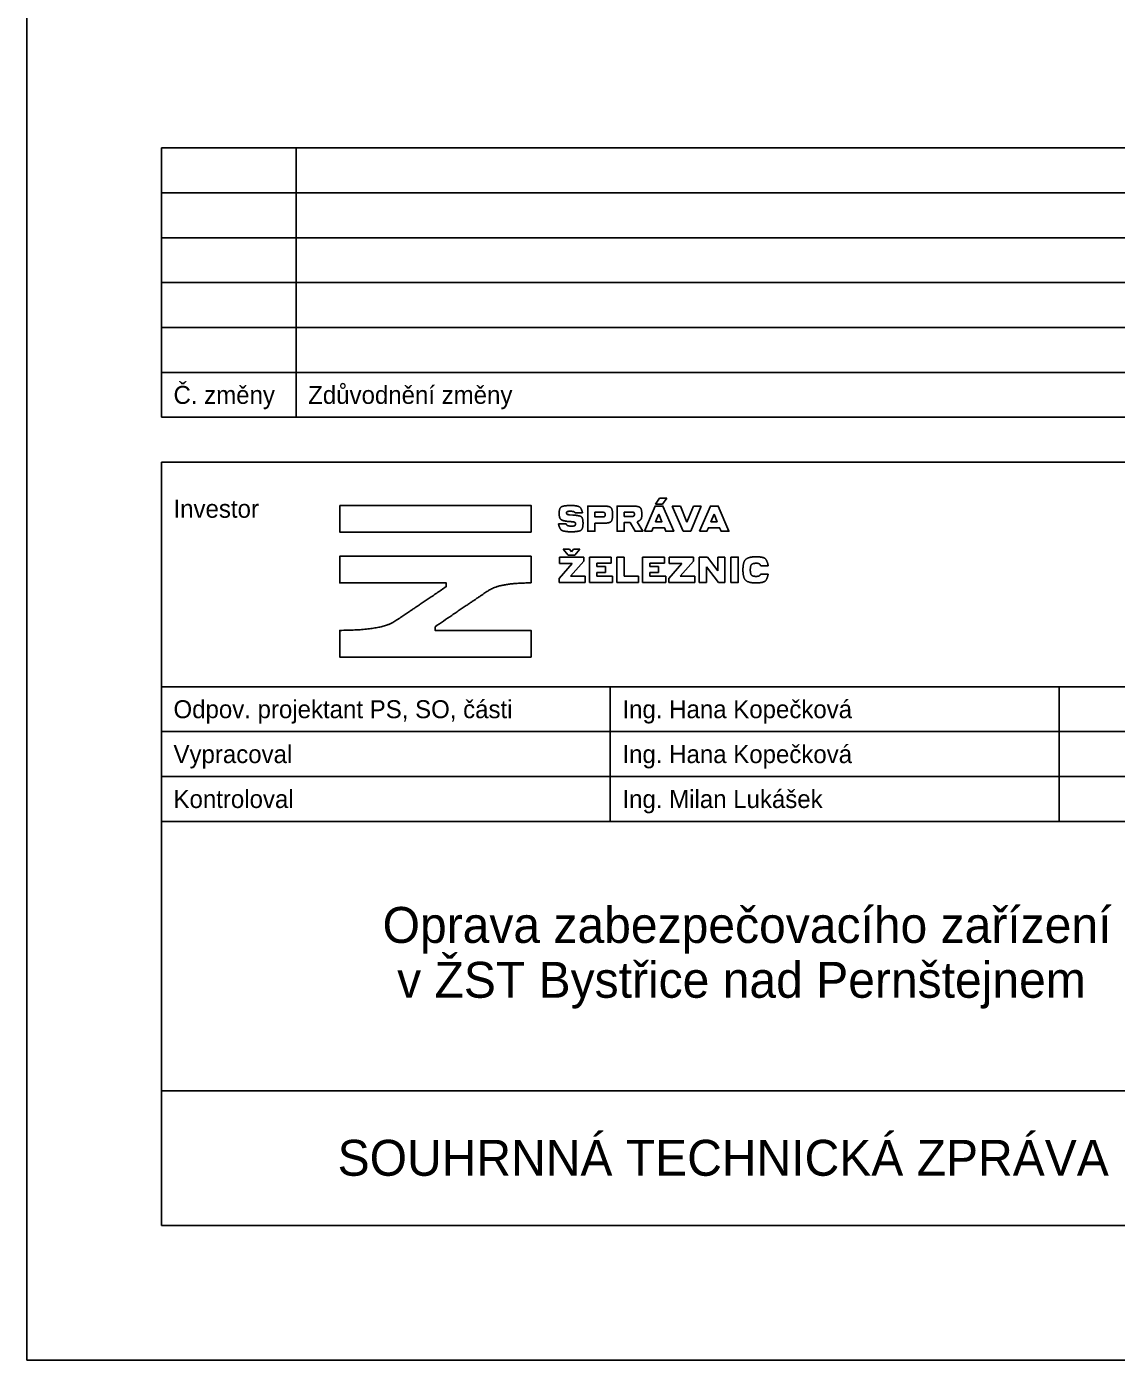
# Model space of a CAD drawing. Extents: x -790471 to -790261, y -984666 to -984369.
# Drawn here: x -790470.6 to -790349.2, y -984665.6 to -984517.1 of the extents above; entities that cross this region are included whole.
import ezdxf

# ---------------------------------------------------------------- set-up
doc = ezdxf.new("R2010")
doc.units = 0
for name, color, linetype in [('logo_sprava_zeleznic', 7, 'Continuous'), ('Ramečky', 7, 'Continuous'), ('Rámečky-tisk', 7, 'Continuous'), ('Text', 7, 'Continuous'), ('Text barevný', 7, 'Continuous')]:
    doc.layers.add(name, color=color, linetype=linetype)

msp = doc.modelspace()

# ---------------------------------------------------------------- linework, layer by layer
at = {"layer": 'logo_sprava_zeleznic'}
for p, q in [((-790400.56, -984570.26), (-790400.12, -984569.6)), ((-790400.12, -984569.6), (-790399.3, -984569.6)), ((-790399.3, -984569.6), (-790399.78, -984570.26)), ((-790409.51, -984571.23), (-790408.69, -984571.23)), ((-790399.78, -984570.26), (-790400.56, -984570.26)), ((-790398.7, -984570.48), (-790397.76, -984570.48)), ((-790397.49, -984573.29), (-790398.7, -984570.48)), ((-790397.76, -984570.48), (-790397.05, -984572.28)), ((-790397.05, -984572.28), (-790396.34, -984570.48)), ((-790395.49, -984570.48), (-790396.64, -984573.29)), ((-790396.34, -984570.48), (-790395.49, -984570.48)), ((-790410.51, -984572.45), (-790411.36, -984572.45)), ((-790409.76, -984571.48), (-790410.15, -984571.45)), ((-790396.64, -984573.29), (-790397.49, -984573.29)), ((-790410.29, -984575.96), (-790410.83, -984575.28)), ((-790410.83, -984575.28), (-790410.14, -984575.28)), ((-790410.14, -984575.28), (-790409.91, -984575.56)), ((-790409.91, -984575.56), (-790409.68, -984575.28)), ((-790409.68, -984575.28), (-790408.97, -984575.28)), ((-790408.97, -984575.28), (-790409.53, -984575.96)), ((-790411.3, -984578.53), (-790409.84, -984576.86)), ((-790411.26, -984576.17), (-790408.55, -984576.17)), ((-790411.26, -984576.86), (-790411.26, -984576.17)), ((-790409.84, -984576.86), (-790411.26, -984576.86)), ((-790409.53, -984575.96), (-790410.29, -984575.96)), ((-790408.55, -984576.63), (-790410.02, -984578.29)), ((-790408.55, -984576.17), (-790408.55, -984576.63)), ((-790407.92, -984576.17), (-790405.49, -984576.17)), ((-790407.92, -984578.99), (-790407.92, -984576.17)), ((-790405.49, -984576.83), (-790407.1, -984576.83)), ((-790407.1, -984576.83), (-790407.1, -984577.2)), ((-790407.1, -984577.2), (-790406.14, -984577.2)), ((-790406.14, -984577.2), (-790406.14, -984577.87)), ((-790405.49, -984576.17), (-790405.49, -984576.83)), ((-790404.86, -984576.17), (-790404.05, -984576.17)), ((-790404.86, -984578.99), (-790404.86, -984576.17)), ((-790404.05, -984576.17), (-790404.05, -984578.28)), ((-790401.99, -984576.17), (-790399.57, -984576.17)), ((-790401.99, -984578.99), (-790401.99, -984576.17)), ((-790399.57, -984576.83), (-790401.18, -984576.83)), ((-790401.18, -984576.83), (-790401.18, -984577.2)), ((-790401.18, -984577.2), (-790400.22, -984577.2)), ((-790400.22, -984577.2), (-790400.22, -984577.87)), ((-790399.57, -984576.17), (-790399.57, -984576.83)), ((-790399.07, -984578.53), (-790397.61, -984576.86)), ((-790399.03, -984576.17), (-790396.33, -984576.17)), ((-790399.03, -984576.86), (-790399.03, -984576.17)), ((-790397.61, -984576.86), (-790399.03, -984576.86)), ((-790396.33, -984576.63), (-790397.8, -984578.29)), ((-790396.33, -984576.17), (-790396.33, -984576.63)), ((-790395.69, -984576.17), (-790394.78, -984576.17)), ((-790395.69, -984578.99), (-790395.69, -984576.17)), ((-790393.53, -984578.99), (-790394.89, -984577.26)), ((-790394.89, -984577.26), (-790394.89, -984578.99)), ((-790394.78, -984576.17), (-790393.63, -984577.68)), ((-790393.63, -984577.68), (-790393.63, -984576.17)), ((-790393.63, -984576.17), (-790392.85, -984576.17)), ((-790392.85, -984576.17), (-790392.85, -984578.99)), ((-790388.84, -984577.12), (-790388.01, -984577.12)), ((-790411.3, -984578.99), (-790411.3, -984578.53)), ((-790410.02, -984578.29), (-790408.39, -984578.29)), ((-790408.39, -984578.29), (-790408.39, -984578.99)), ((-790406.14, -984577.87), (-790407.1, -984577.87)), ((-790407.1, -984577.87), (-790407.1, -984578.3)), ((-790407.1, -984578.3), (-790405.34, -984578.3)), ((-790405.34, -984578.3), (-790405.34, -984578.99)), ((-790404.05, -984578.28), (-790402.47, -984578.28)), ((-790402.47, -984578.28), (-790402.47, -984578.99)), ((-790400.22, -984577.87), (-790401.18, -984577.87)), ((-790401.18, -984577.87), (-790401.18, -984578.3)), ((-790401.18, -984578.3), (-790399.41, -984578.3)), ((-790399.41, -984578.3), (-790399.41, -984578.99)), ((-790399.07, -984578.99), (-790399.07, -984578.53)), ((-790397.8, -984578.29), (-790396.16, -984578.29)), ((-790396.16, -984578.29), (-790396.16, -984578.99)), ((-790388.01, -984578.05), (-790388.83, -984578.05)), ((-790408.39, -984578.99), (-790411.3, -984578.99)), ((-790405.34, -984578.99), (-790407.92, -984578.99)), ((-790402.47, -984578.99), (-790404.86, -984578.99)), ((-790399.41, -984578.99), (-790401.99, -984578.99)), ((-790396.16, -984578.99), (-790399.07, -984578.99)), ((-790394.89, -984578.99), (-790395.69, -984578.99)), ((-790392.85, -984578.99), (-790393.53, -984578.99))]:
    msp.add_line(p, q, dxfattribs=at)
for points in [[(-790435.73, -984570.4), (-790414.41, -984570.4), (-790414.41, -984573.38), (-790435.73, -984573.38)], [(-790401.8, -984573.29), (-790400.98, -984573.29), (-790400.82, -984572.89), (-790399.57, -984572.89), (-790399.41, -984573.29), (-790398.53, -984573.29), (-790399.73, -984570.48), (-790400.6, -984570.48)], [(-790395.65, -984573.29), (-790394.83, -984573.29), (-790394.66, -984572.89), (-790393.42, -984572.89), (-790393.26, -984573.29), (-790392.38, -984573.29), (-790393.57, -984570.48), (-790394.45, -984570.48)], [(-790400.19, -984571.39), (-790399.85, -984572.23), (-790400.54, -984572.23)], [(-790394.04, -984571.39), (-790393.7, -984572.23), (-790394.39, -984572.23)], [(-790392.16, -984576.17), (-790391.35, -984576.17), (-790391.35, -984578.99), (-790392.16, -984578.99)]]:
    msp.add_lwpolyline(points, close=True, dxfattribs=at)
for points in [[(-790406.38, -984570.48), (-790408.11, -984570.48), (-790408.11, -984573.29), (-790407.3, -984573.29), (-790407.3, -984572.39), (-790406.38, -984572.39)], [(-790406.48, -984571.69), (-790407.3, -984571.69), (-790407.3, -984571.17), (-790406.48, -984571.17)], [(-790403.12, -984570.48), (-790404.84, -984570.48), (-790404.84, -984573.29), (-790404.03, -984573.29), (-790404.03, -984572.31), (-790403.39, -984572.31), (-790402.84, -984573.29), (-790401.98, -984573.29), (-790402.59, -984572.22)], [(-790403.22, -984571.64), (-790404.03, -984571.64), (-790404.03, -984571.16), (-790403.22, -984571.16)], [(-790423.87, -984579.46), (-790423.87, -984579.04), (-790435.73, -984579.04), (-790435.73, -984576.07), (-790414.41, -984576.07), (-790414.41, -984579.04)], [(-790425.1, -984583.91), (-790425.1, -984584.32), (-790414.41, -984584.32), (-790414.41, -984587.3), (-790435.73, -984587.3), (-790435.73, -984584.32), (-790435.71, -984584.32)]]:
    msp.add_lwpolyline(points, dxfattribs=at)
for centre, radius, start, end in [((-790411.9, -984593.14), 21.01, 84.2634, 85.3384), ((-790461.18, -984526.6), 64.69, 304.0901, 305.2133), ((-790124.63, -985020.54), 530.02, 124.292, 124.5333)]:
    msp.add_arc(centre, radius, start, end, dxfattribs=at)
for points in [[(-790410.05, -984570.42), (-790410.77, -984570.42), (-790411.29, -984570.71), (-790411.29, -984571.28)], [(-790411.29, -984571.28), (-790411.29, -984571.83), (-790410.87, -984572.14), (-790410.19, -984572.2)], [(-790410.46, -984571.24), (-790410.46, -984571.12), (-790410.3, -984571.06), (-790410.05, -984571.06)], [(-790410.15, -984571.45), (-790410.35, -984571.43), (-790410.46, -984571.36), (-790410.46, -984571.24)], [(-790408.69, -984571.23), (-790408.77, -984570.87), (-790409.09, -984570.42), (-790410.05, -984570.42)], [(-790410.05, -984571.06), (-790409.73, -984571.06), (-790409.55, -984571.17), (-790409.51, -984571.23)], [(-790406.48, -984571.17), (-790406.27, -984571.17), (-790406.17, -984571.26), (-790406.17, -984571.43)], [(-790405.34, -984571.43), (-790405.34, -984570.8), (-790405.73, -984570.48), (-790406.38, -984570.48)], [(-790403.22, -984571.16), (-790403.02, -984571.16), (-790402.91, -984571.23), (-790402.91, -984571.4)], [(-790402.08, -984571.4), (-790402.08, -984570.79), (-790402.49, -984570.48), (-790403.12, -984570.48)], [(-790411.36, -984572.45), (-790411.29, -984572.84), (-790410.93, -984573.34), (-790409.92, -984573.34)], [(-790409.92, -984572.71), (-790410.28, -984572.71), (-790410.46, -984572.57), (-790410.51, -984572.45)], [(-790409.92, -984573.34), (-790409.08, -984573.34), (-790408.63, -984573), (-790408.63, -984572.4)], [(-790409.47, -984572.46), (-790409.47, -984572.61), (-790409.6, -984572.71), (-790409.92, -984572.71)], [(-790409.8, -984572.23), (-790409.6, -984572.26), (-790409.47, -984572.31), (-790409.47, -984572.46)], [(-790408.63, -984572.4), (-790408.63, -984571.79), (-790409.03, -984571.53), (-790409.76, -984571.48)], [(-790406.17, -984571.43), (-790406.17, -984571.59), (-790406.27, -984571.69), (-790406.48, -984571.69)], [(-790406.38, -984572.39), (-790405.73, -984572.39), (-790405.34, -984572.06), (-790405.34, -984571.43)], [(-790402.91, -984571.4), (-790402.91, -984571.55), (-790403.02, -984571.64), (-790403.22, -984571.64)], [(-790402.59, -984572.22), (-790402.27, -984572.08), (-790402.08, -984571.8), (-790402.08, -984571.4)], [(-790389.36, -984576.13), (-790390.22, -984576.13), (-790390.82, -984576.73), (-790390.82, -984577.58)], [(-790390, -984577.58), (-790390, -984577.18), (-790389.76, -984576.85), (-790389.36, -984576.85)], [(-790388.01, -984577.12), (-790388.06, -984576.8), (-790388.4, -984576.13), (-790389.36, -984576.13)], [(-790389.36, -984576.85), (-790389.02, -984576.85), (-790388.88, -984577.05), (-790388.84, -984577.12)], [(-790390.82, -984577.58), (-790390.82, -984578.43), (-790390.22, -984579.04), (-790389.36, -984579.04)], [(-790389.36, -984578.31), (-790389.76, -984578.31), (-790390, -984577.99), (-790390, -984577.58)], [(-790389.36, -984579.04), (-790388.37, -984579.04), (-790388.05, -984578.31), (-790388.01, -984578.05)], [(-790388.83, -984578.05), (-790388.87, -984578.12), (-790389.02, -984578.31), (-790389.36, -984578.31)], [(-790435.71, -984584.32), (-790431.06, -984584.31), (-790428.08, -984582.3), (-790424.92, -984580.18)], [(-790414.41, -984579.04), (-790417.9, -984579.04), (-790420.38, -984580.71), (-790423.25, -984582.65)]]:
    msp.add_open_spline(points, degree=2, dxfattribs=at)
at = {"layer": 'Ramečky'}
for p, q in [((-790275.59, -984530.6), (-790455.59, -984530.6)), ((-790455.59, -984530.6), (-790455.59, -984560.6)), ((-790440.59, -984530.6), (-790440.59, -984560.6)), ((-790305.59, -984535.6), (-790455.59, -984535.6)), ((-790305.59, -984540.6), (-790455.59, -984540.6)), ((-790305.59, -984545.6), (-790455.59, -984545.6)), ((-790305.59, -984550.6), (-790455.59, -984550.6)), ((-790305.59, -984555.6), (-790455.59, -984555.6)), ((-790275.59, -984560.6), (-790455.59, -984560.6)), ((-790275.59, -984565.6), (-790455.59, -984565.6)), ((-790455.59, -984650.6), (-790455.59, -984565.6)), ((-790455.59, -984590.6), (-790325.59, -984590.6)), ((-790455.59, -984595.6), (-790325.59, -984595.6)), ((-790455.59, -984600.6), (-790325.59, -984600.6)), ((-790455.59, -984605.6), (-790325.59, -984605.6)), ((-790455.59, -984635.6), (-790275.59, -984635.6)), ((-790455.59, -984650.6), (-790275.59, -984650.6))]:
    msp.add_line(p, q, dxfattribs=at)
for points in [[(-790405.59, -984590.6), (-790405.59, -984605.6)], [(-790355.59, -984590.6), (-790355.59, -984605.6)]]:
    msp.add_lwpolyline(points, dxfattribs=at)
at = {"layer": 'Rámečky-tisk'}
msp.add_line((-790470.59, -984368.6), (-790470.59, -984665.6), dxfattribs=at)
msp.add_lwpolyline([(-790470.59, -984665.6), (-790260.59, -984665.6), (-790260.59, -984368.6)], dxfattribs=at)

# ---------------------------------------------------------------- texts
at = {"layer": 'Text'}
for s, p in [('Č. změny', (-790454.24, -984559.1)), ('Zdůvodnění změny', (-790439.24, -984559.1)), ('Investor', (-790454.24, -984571.78)), ('Odpov. projektant PS, SO, části', (-790454.24, -984594.1)), ('Ing. Hana Kopečková', (-790404.24, -984594.1)), ('Vypracoval', (-790454.24, -984599.1)), ('Ing. Hana Kopečková', (-790404.24, -984599.1)), ('Kontroloval', (-790454.24, -984604.1)), ('Ing. Milan Lukášek', (-790404.24, -984604.1))]:
    msp.add_text(s, height=2, dxfattribs=at).set_placement(p)
at = {"layer": 'Text barevný'}
for s, p in [('Oprava zabezpečovacího zařízení', (-790430.95, -984619.12)), ('v ŽST Bystřice nad Pernštejnem', (-790429.33, -984625.23)), ('SOUHRNNÁ TECHNICKÁ ZPRÁVA', (-790435.96, -984645.05))]:
    msp.add_text(s, height=4, dxfattribs=at).set_placement(p)

doc.saveas('drawing.dxf')
